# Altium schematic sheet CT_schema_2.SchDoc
size 276 x 169 mm
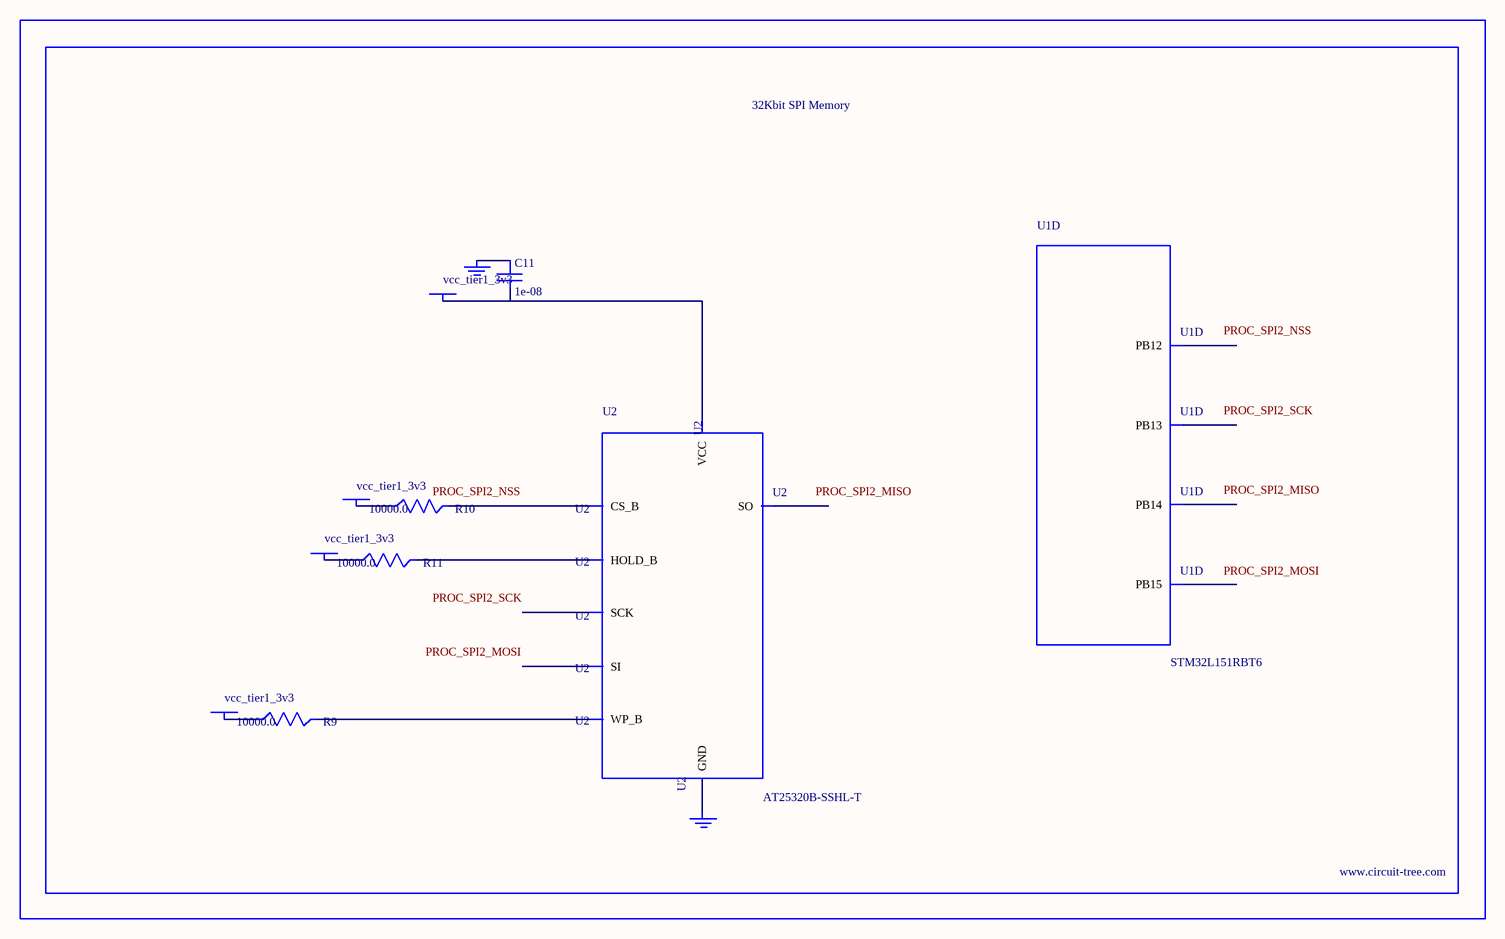
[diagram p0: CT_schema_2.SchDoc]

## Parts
BORDER1  (no value)
C11  1e-08  [C0402]
GND_INSTANCE_1_0  (no value)
GND_INSTANCE_1_1  (no value)
POWER_INSTANCE_1_0  vcc_tier1_3v3
POWER_INSTANCE_1_1  vcc_tier1_3v3
POWER_INSTANCE_1_2  vcc_tier1_3v3
POWER_INSTANCE_1_3  vcc_tier1_3v3
R9  10000.0  [R0603]
R10  10000.0  [R0603]
R11  10000.0  [R0603]
U1  STM32L151RBT6  [LQFP64]  (part D of 7)
U2  AT25320B-SSHL-T  [SOIC-8]

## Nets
NetC11_1: C11.1 GND_INSTANCE_1_0.0(GND)
NetC11_2: C11.2 POWER_INSTANCE_1_3.0(PWR) U2.8(VCC)
NetGND_INSTANCE_1_1_0: GND_INSTANCE_1_1.0(GND) U2.4(GND)
NetPOWER_INSTANCE_1_0_0: POWER_INSTANCE_1_0.0(PWR) R10.1
NetPOWER_INSTANCE_1_1_0: POWER_INSTANCE_1_1.0(PWR) R9.1
NetPOWER_INSTANCE_1_2_0: POWER_INSTANCE_1_2.0(PWR) R11.1
NetR9_2: R9.2 U2.3(WP_B)
NetR10_2: R10.2 U2.1(CS_B)
NetR11_2: R11.2 U2.7(HOLD_B)

Not connected (* = marked no-connect by the designer): U1 33(PB12) 34(PB13) 35(PB14) 36(PB15); U2 2(SO) 5(SI) 6(SCK)

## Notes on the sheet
- Labels drawn without touching a wire or pin: PROC_SPI2_MISO, PROC_SPI2_MOSI, PROC_SPI2_NSS, PROC_SPI2_SCK

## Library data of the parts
BORDER1 = BORDER_PAGE1
C11 = C0402C103K3RAC
GND_INSTANCE_1_0 GND_INSTANCE_1_1 = GND
POWER_INSTANCE_1_0-POWER_INSTANCE_1_3 = PWR
R9-R11 = RC0603JR-0710KL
